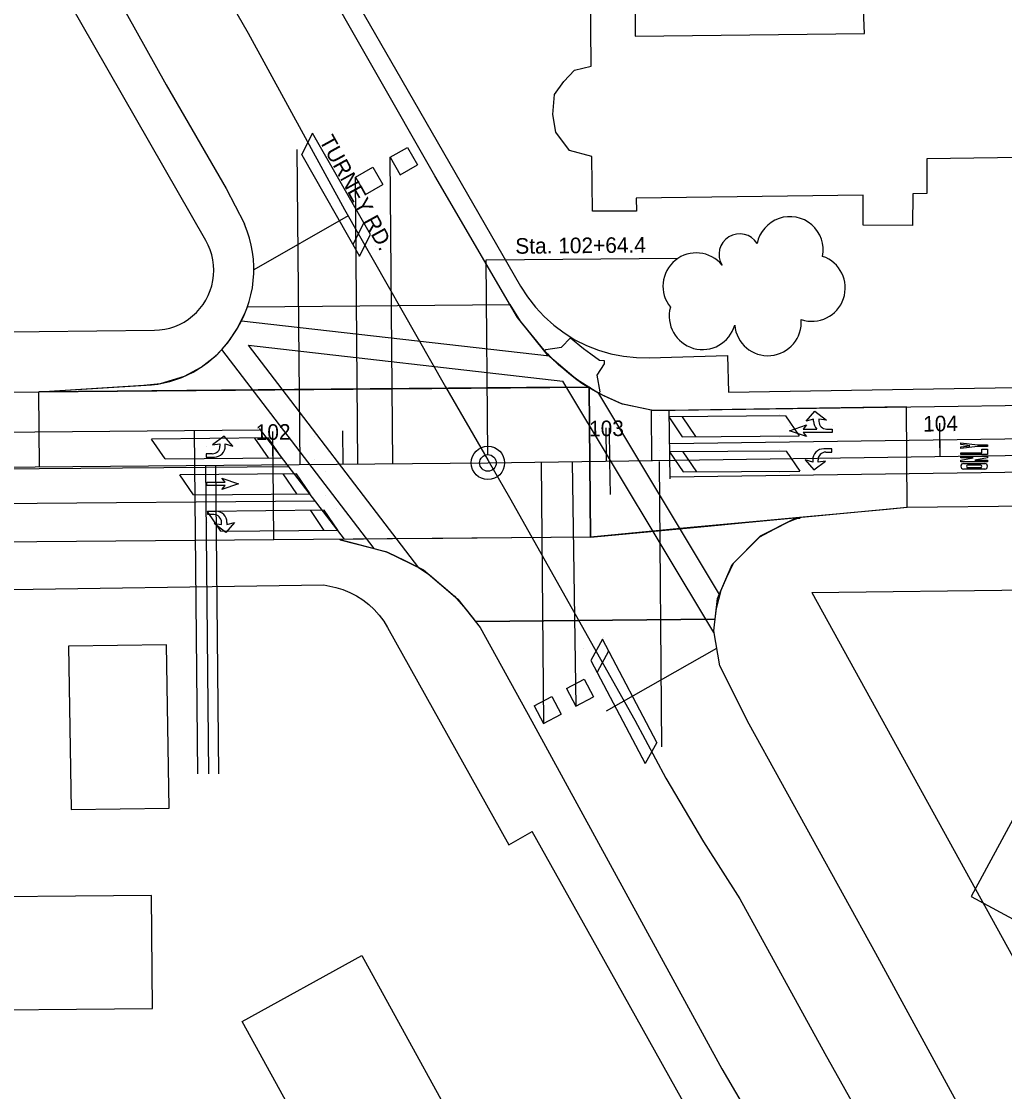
# Model space of a CAD drawing. Extents: x -2233 to 187241, y 4582 to 150524.
# Drawn here: x 110067.4 to 110362.1, y 59307.9 to 59628.8 of the extents above; entities that cross this region are included whole.
import ezdxf

# ---------------------------------------------------------------- set-up
doc = ezdxf.new("R2010")
doc.units = 0
for name, color, linetype in [('AP_X_Misc', 7, 'Continuous'), ('BLDG', 7, 'Continuous'), ('GE_X_CL_100', 7, 'Continuous'), ('GE_X_CL_20', 7, 'Continuous'), ('GE_X_CL_2000', 7, 'Continuous'), ('GE_X_CL_50', 7, 'Continuous'), ('PM_P_Cells', 7, 'Continuous'), ('PM_P_Channelizing_Line', 7, 'Continuous'), ('PM_P_CL_Double_Solid', 7, 'Continuous'), ('PM_P_Crosswalk', 7, 'Continuous'), ('PM_P_Stop_Line', 7, 'Continuous'), ('PM_P_Text', 7, 'Continuous'), ('PV_P_Curb_Ramp', 7, 'Continuous'), ('ROAD', 7, 'Continuous'), ('RW_X_Fee_RW', 7, 'Continuous'), ('SG_P_Detection', 7, 'Continuous'), ('TREES', 7, 'Continuous')]:
    doc.layers.add(name, color=color, linetype=linetype)

msp = doc.modelspace()

# ---------------------------------------------------------------- linework, layer by layer
at = {"layer": 'AP_X_Misc'}
for p, q in [((110072.78, 59495.23), (110072.58, 59517.73)), ((110237.77, 59496.68), (110237.58, 59519.18)), ((110256.34, 59497.13), (110256.2, 59512.13)), ((110332.76, 59498.24), (110332.63, 59513.24)), ((110142.98, 59473.35), (110142.78, 59495.84)), ((110237.97, 59474.18), (110237.77, 59496.68)), ((110332.89, 59483.14), (110332.76, 59498.24))]:
    msp.add_line(p, q, dxfattribs=at)
for points in [[(110072.58, 59517.73), (110104.09, 59519.71), (110109.1, 59520.24), (110116.2, 59522.4), (110121.22, 59525.11), (110125.74, 59528.68), (110129.1, 59532.38), (110131.81, 59536.32), (110134.36, 59541.23), (110135.14, 59543.28), (110213.72, 59543.97), (110216.86, 59538.98), (110223.94, 59530.24), (110226.83, 59527.35), (110231.76, 59523.16), (110236.09, 59519.99), (110237.42, 59519.18), (110218.77, 59519.02), (110160.18, 59518.5), (110127.35, 59518.21), (110096.1, 59517.93)], [(110332.63, 59513.24), (110260.8, 59512.19), (110256.61, 59512.13), (110254.2, 59512.65), (110247.28, 59514.16), (110241.89, 59516.57), (110238.33, 59518.57), (110237.58, 59519.18), (110237.97, 59474.18), (110273.14, 59477.5), (110301.72, 59480.2), (110326.85, 59482.57), (110332.89, 59483.14)], [(110162.76, 59473.41), (110167.4, 59472.25), (110172.26, 59470.99), (110177.12, 59469.61), (110182.07, 59467.21), (110186.33, 59465.14), (110189.68, 59462.85), (110193.74, 59459.38), (110197.2, 59456.43), (110200.55, 59452.59), (110202.49, 59450.12), (110203.47, 59448.88), (110275.36, 59449.51), (110275.73, 59452.83), (110277.13, 59458.26), (110278.79, 59462.18), (110280.8, 59466.33), (110284.26, 59469.81), (110288.66, 59474.24), (110292.95, 59476.56), (110297.49, 59478.88), (110300.56, 59480.09), (110287.73, 59478.88), (110267.91, 59477.01), (110249.29, 59475.25), (110237.92, 59474.18), (110214.34, 59473.97), (110193.67, 59473.79), (110177.03, 59473.65)]]:
    msp.add_lwpolyline(points, close=True, dxfattribs=at)
at = {"layer": 'BLDG'}
for points in [[(110251.27, 59638.74), (110251.33, 59624.37), (110320.12, 59625.2), (110319.25, 59644.45)], [(110388.19, 59588.37), (110338.79, 59587.63), (110338.76, 59577.18), (110334.53, 59577.15), (110334.44, 59567.59), (110319.63, 59567.78), (110319.63, 59576.7), (110251.62, 59575.87), (110251.72, 59571.89), (110238.5, 59571.88), (110238.39, 59588.37), (110231.6, 59590.16), (110227.54, 59595.58), (110226.62, 59600.97), (110227.12, 59606.88), (110229.98, 59610.82), (110233.15, 59614.2), (110238.17, 59615.43), (110237.98, 59638.47)]]:
    msp.add_lwpolyline(points, dxfattribs=at)
for points in [[(110378.28, 59352.16), (110396.6, 59386), (110414.97, 59376.05), (110424.32, 59393.34), (110405.97, 59403.27), (110424.27, 59437.1), (110397.99, 59451.32), (110352.02, 59366.37)], [(110111.68, 59392.91), (110110.89, 59441.88), (110081.5, 59441.41), (110082.29, 59392.45)], [(110038.31, 59332.14), (110106.61, 59332.74), (110106.31, 59366.71), (110038.02, 59366.12)], [(110169.36, 59348.65), (110206.85, 59280.54), (110170.98, 59260.79), (110133.5, 59328.92)]]:
    msp.add_lwpolyline(points, close=True, dxfattribs=at)
at = {"layer": 'GE_X_CL_100'}
for p, q in [((110342.76, 59498.38), (110342.61, 59508.38)), ((110142.78, 59495.84), (110142.69, 59505.84)), ((110242.77, 59496.93), (110242.62, 59506.93))]:
    msp.add_line(p, q, dxfattribs=at)
msp.add_circle((110207.2, 59496.41), 5, dxfattribs=at)
msp.add_circle((110207.2, 59496.41), 5, dxfattribs=at)
at = {"layer": 'GE_X_CL_20'}
for p, q in [((110207.2, 59496.41), (110955.68, 59507.28)), ((109868.59, 59493.43), (110207.2, 59496.41))]:
    msp.add_line(p, q, dxfattribs=at)
at = {"layer": 'GE_X_CL_2000'}
for p, q in [((110207.2, 59496.41), (110955.68, 59507.28)), ((109868.59, 59493.43), (110207.2, 59496.41))]:
    msp.add_line(p, q, dxfattribs=at)
for points in [[(109980.49, 59891.06), (109998.03, 59860.35), (110019.59, 59824.07), (110044.24, 59782.92), (110087.15, 59709.85), (110109.38, 59670.9), (110118.75, 59654.26), (110135.33, 59625.36), (110164.25, 59572.39), (110194.51, 59519.21), (110207.31, 59497.1)], [(110207.31, 59497.1), (110213.69, 59486.07), (110251.26, 59419.29), (110260.51, 59401.88), (110271.8, 59382.77), (110282.72, 59365.7), (110308.21, 59319.29), (110329.38, 59281.54), (110342.24, 59258.86), (110351.38, 59242.1)]]:
    msp.add_lwpolyline(points, dxfattribs=at)
at = {"layer": 'GE_X_CL_50'}
for p, q in [((110206.67, 59557.29), (110264.02, 59557.8)), ((110207.18, 59498.91), (110206.67, 59557.29)), ((110242.77, 59496.93), (110242.7, 59501.93)), ((110342.76, 59498.38), (110342.69, 59503.38)), ((110142.78, 59495.84), (110142.73, 59500.84))]:
    msp.add_line(p, q, dxfattribs=at)
msp.add_circle((110207.2, 59496.41), 2.5, dxfattribs=at)
msp.add_circle((110207.2, 59496.41), 2.5, dxfattribs=at)
at = {"layer": 'PM_P_Cells'}
for p, q in [((110302.58, 59508.9), (110305.14, 59511.9)), ((110305.14, 59511.9), (110308.66, 59509.24)), ((110304.82, 59509.57), (110302.58, 59508.9)), ((110304.82, 59508.9), (110304.82, 59509.57)), ((110308.66, 59509.24), (110306.42, 59509.57)), ((110306.42, 59509.57), (110306.42, 59508.87)), ((110297.64, 59506.07), (110302.64, 59507.81)), ((110297.64, 59507.74), (110297.64, 59507.74)), ((110302.64, 59504.34), (110297.64, 59506.07)), ((110302.64, 59507.81), (110301.64, 59506.57)), ((110310.39, 59505.57), (110301.64, 59505.57)), ((110301.64, 59505.57), (110302.64, 59504.34)), ((110308.72, 59506.57), (110310.39, 59506.57)), ((110310.39, 59507.74), (110310.39, 59507.74)), ((110310.39, 59506.57), (110310.39, 59505.57)), ((110128.16, 59504.49), (110124.64, 59501.82)), ((110124.64, 59501.82), (110126.88, 59502.15)), ((110126.88, 59502.15), (110126.88, 59501.45)), ((110130.72, 59501.49), (110128.16, 59504.49)), ((110128.48, 59501.49), (110128.48, 59502.15)), ((110128.48, 59502.15), (110130.72, 59501.49)), ((110348.94, 59501.91), (110348.94, 59502.41)), ((110348.94, 59502.41), (110353.94, 59501.83)), ((110351.61, 59501.58), (110348.94, 59501.91)), ((110353.94, 59501.83), (110356.94, 59501.83)), ((110356.94, 59501.83), (110356.94, 59501.33)), ((110122.72, 59501.49), (110122.72, 59501.49)), ((110124.58, 59499.15), (110122.72, 59499.15)), ((110122.72, 59499.15), (110122.72, 59498.15)), ((110130.72, 59501.49), (110130.72, 59501.49)), ((110310.32, 59500.65), (110307.84, 59500.65)), ((110308.45, 59499.65), (110310.32, 59499.65)), ((110310.32, 59499.65), (110310.32, 59500.65)), ((110348.94, 59501.25), (110351.61, 59501.58)), ((110353.94, 59501.33), (110348.94, 59500.75)), ((110348.94, 59500.75), (110348.94, 59501.25)), ((110348.94, 59498.91), (110348.94, 59499.41)), ((110348.94, 59499.41), (110355.28, 59499.41)), ((110356.94, 59498.91), (110348.94, 59498.91)), ((110348.94, 59498.5), (110348.94, 59498.5)), ((110356.94, 59501.33), (110353.94, 59501.33)), ((110355.28, 59499.41), (110355.28, 59500.58)), ((110355.28, 59500.58), (110356.94, 59500.58)), ((110356.94, 59500.58), (110356.94, 59498.91)), ((110356.94, 59498.5), (110356.94, 59498.5)), ((110122.72, 59498.15), (110125.2, 59498.15)), ((110302.32, 59497.32), (110302.32, 59497.32)), ((110304.56, 59496.65), (110302.32, 59497.32)), ((110302.32, 59497.32), (110304.88, 59494.32)), ((110304.56, 59497.32), (110304.56, 59496.65)), ((110304.88, 59494.32), (110308.4, 59496.99)), ((110306.16, 59496.65), (110306.16, 59497.36)), ((110308.4, 59496.99), (110306.16, 59496.65)), ((110310.32, 59497.32), (110310.32, 59497.32)), ((110348.94, 59497.91), (110348.94, 59498.41)), ((110348.94, 59498.41), (110356.94, 59498.41)), ((110348.94, 59497.25), (110352.69, 59497.91)), ((110352.69, 59497.91), (110348.94, 59497.91)), ((110348.94, 59496.75), (110348.94, 59497.25)), ((110356.94, 59496.75), (110348.94, 59496.75)), ((110349.78, 59496.25), (110356.11, 59496.25)), ((110354.95, 59495.75), (110350.94, 59495.75)), ((110356.94, 59497.91), (110353.19, 59497.25)), ((110353.19, 59497.25), (110356.94, 59497.25)), ((110356.94, 59498.41), (110356.94, 59497.91)), ((110356.94, 59497.25), (110356.94, 59496.75)), ((110350.94, 59494.58), (110349.78, 59494.58)), ((110350.94, 59495.08), (110350.94, 59494.58)), ((110350.94, 59494.58), (110350.94, 59495.08)), ((110350.94, 59495.08), (110354.95, 59495.08)), ((110354.95, 59494.58), (110350.94, 59494.58)), ((110354.95, 59494.58), (110354.95, 59495.08)), ((110354.95, 59495.08), (110354.95, 59494.58)), ((110356.11, 59494.58), (110354.95, 59494.58)), ((110122.97, 59489.65), (110122.97, 59490.65)), ((110122.97, 59490.65), (110128.47, 59490.65)), ((110122.97, 59490.15), (110122.97, 59490.15)), ((110128.47, 59489.65), (110122.97, 59489.65)), ((110128.47, 59490.65), (110127.47, 59491.89)), ((110127.47, 59491.89), (110132.47, 59490.15)), ((110132.47, 59490.15), (110127.47, 59488.41)), ((110127.47, 59488.41), (110128.47, 59489.65)), ((110132.47, 59490.15), (110132.47, 59490.15)), ((110123.2, 59480.91), (110123.2, 59481.91)), ((110123.2, 59481.91), (110125.67, 59481.91)), ((110125.06, 59480.91), (110123.2, 59480.91)), ((110123.2, 59478.58), (110123.2, 59478.58)), ((110128.64, 59475.58), (110125.12, 59478.24)), ((110125.12, 59478.24), (110127.36, 59477.91)), ((110127.36, 59477.91), (110127.36, 59478.61)), ((110131.2, 59478.58), (110128.64, 59475.58)), ((110128.96, 59478.58), (110128.96, 59477.91)), ((110128.96, 59477.91), (110131.2, 59478.58)), ((110131.2, 59478.58), (110131.2, 59478.58))]:
    msp.add_line(p, q, dxfattribs=at)
msp.add_lwpolyline([(110301.64, 59506.57), (110305.75, 59506.57)], dxfattribs=at)
for centre, radius, start, end in [((110308.11, 59508.85), 3.28, 179.0915, 224.0466), ((110308.72, 59508.87), 2.3, 180, 270), ((110124.58, 59501.45), 2.3, 270, 0), ((110125.2, 59501.44), 3.28, 270, 0.9085), ((110307.84, 59497.37), 3.28, 90, 180.9085), ((110308.45, 59497.36), 2.3, 90, 180), ((110349.78, 59495.41), 0.833, 90, 270), ((110350.94, 59495.41), 0.333, 90, 270), ((110354.95, 59495.41), 0.333, 270, 90), ((110356.11, 59495.41), 0.833, 270, 90), ((110125.06, 59478.61), 2.3, 0, 90), ((110125.67, 59478.63), 3.28, 359.0915, 90)]:
    msp.add_arc(centre, radius, start, end, dxfattribs=at)
at = {"layer": 'PM_P_Channelizing_Line'}
for p, q in [((110261.69, 59502.2), (110606.03, 59507.2)), ((110022.11, 59494.28), (110147.48, 59495.39)), ((110155.46, 59484.96), (110050.88, 59484.03))]:
    msp.add_line(p, q, dxfattribs=at)
at = {"layer": 'PM_P_CL_Double_Solid'}
for p, q in [((110022.01, 59505.28), (110138.76, 59506.31)), ((110261.84, 59492.21), (110616.44, 59497.35))]:
    msp.add_line(p, q, dxfattribs=at)
at = {"layer": 'PM_P_Crosswalk'}
for p, q in [((110133.32, 59539), (110225.68, 59528.49)), ((110186.44, 59465), (110135.39, 59531.71)), ((110135.39, 59531.71), (110229.63, 59520.99)), ((110173.09, 59470.78), (110127.44, 59530.42)), ((110274.91, 59445.56), (110229.63, 59520.99)), ((110276.59, 59457), (110240.45, 59517.21))]:
    msp.add_line(p, q, dxfattribs=at)
at = {"layer": 'PM_P_Stop_Line'}
for p, q in [((110165.33, 59570.49), (110137.01, 59554.38)), ((110261.85, 59491.69), (110261.55, 59512.2)), ((110164.21, 59473.53), (110138.75, 59506.79)), ((110242.73, 59422.05), (110275.81, 59440.81))]:
    msp.add_line(p, q, dxfattribs=at)
at = {"layer": 'PM_P_Text'}
for p, q in [((110150.87, 59495.92), (110150.04, 59590.4)), ((110178.69, 59496.16), (110177.88, 59588.08)), ((110168.22, 59496.07), (110167.46, 59582.11)), ((110119.19, 59506.14), (110120.1, 59403.15)), ((110163.78, 59496.03), (110163.69, 59506.03)), ((110243.77, 59496.94), (110243.62, 59506.94)), ((110122.58, 59495.67), (110123.4, 59403.18)), ((110125.58, 59495.69), (110126.4, 59403.2)), ((110223.15, 59496.55), (110223.84, 59418.26)), ((110232.49, 59496.78), (110233.56, 59423.42)), ((110243.91, 59486.94), (110243.77, 59496.94)), ((110258.52, 59496.86), (110259.27, 59411.25))]:
    msp.add_line(p, q, dxfattribs=at)
at = {"layer": 'PV_P_Curb_Ramp'}
msp.add_lwpolyline([(110224.15, 59530.13), (110224.53, 59530.45), (110229.26, 59531.14), (110231.94, 59533.95), (110235.81, 59530.76), (110238, 59529.1), (110240.62, 59527.21), (110242.08, 59527.14), (110242.03, 59526.12), (110239.85, 59522.76), (110240.71, 59517.79), (110240.5, 59517.34), (110239.45, 59517.85), (110237.58, 59518.94), (110235.38, 59520.29), (110233.4, 59521.66), (110231.45, 59523.25), (110229.92, 59524.52), (110228.39, 59525.86), (110226.88, 59527.32), (110225.43, 59528.74), (110224.66, 59529.46)], close=True, dxfattribs=at)
at = {"layer": 'ROAD'}
for p, q in [((110135.14, 59543.28), (110213.72, 59543.97)), ((110256.2, 59512.13), (110919.2, 59521.75)), ((110021.58, 59517.28), (110072.58, 59517.73)), ((110072.58, 59517.73), (110106.33, 59519.85)), ((110072.58, 59517.73), (110237.58, 59519.18)), ((110237.97, 59474.18), (110332.89, 59483.14)), ((110332.89, 59483.14), (110442.97, 59484.5)), ((110142.98, 59473.35), (110059.98, 59472.61)), ((110237.97, 59474.18), (110142.98, 59473.35)), ((110275.36, 59449.51), (110203.47, 59448.88))]:
    msp.add_line(p, q, dxfattribs=at)
for points in [[(110256.2, 59512.23), (110247.5, 59514.06), (110240.48, 59517.2), (110233.65, 59521.55), (110225.04, 59528.88), (110216.04, 59539.99), (110191.31, 59582.54), (110118.93, 59709.36), (110052.23, 59823.22), (109992.15, 59921.86)], [(109993.05, 59818.6), (109998.28, 59809.12), (110027.42, 59758.31), (110077.35, 59669.8), (110110.71, 59609.85), (110128.73, 59578.72), (110134.1, 59568.34), (110134.21, 59568)], [(110500.24, 59028.14), (110497, 59033.97), (110407.47, 59195), (110323.47, 59349.24), (110285.49, 59418.02), (110276.67, 59435.6), (110274.96, 59446.01), (110276.06, 59455.76), (110280.39, 59465.92), (110288.93, 59474.51), (110299.18, 59479.74), (110300.82, 59479.88)], [(110162.76, 59473.41), (110162.93, 59473.4), (110176.56, 59469.88), (110187.86, 59464.4), (110198.18, 59455.59), (110204.91, 59447.06), (110220.32, 59418.96), (110277.3, 59314.73), (110306.26, 59265.16)]]:
    msp.add_lwpolyline(points, dxfattribs=at)
for centre, radius, start, end in [((110102.9, 59554.44), 34.12, 325.3465, 23.4134), ((110103.12, 59552.61), 32.92, 275.5964, 327.7335)]:
    msp.add_arc(centre, radius, start, end, dxfattribs=at)
at = {"layer": 'RW_X_Fee_RW'}
for p, q in [((110122.63, 59563.15), (110067.59, 59659.24)), ((110255.56, 59527.96), (110278.96, 59528.68)), ((110278.96, 59528.68), (110279.3, 59517.69)), ((110304.28, 59457.52), (110480.21, 59459.77)), ((110304.28, 59457.52), (110391.88, 59298.63)), ((110177.13, 59447.07), (110213.51, 59381.92)), ((110213.51, 59381.92), (110220.5, 59385.82))]:
    msp.add_line(p, q, dxfattribs=at)
for points in [[(110124.05, 59710.81), (110152.77, 59660.94), (110181.43, 59611.19), (110216.96, 59549.48)], [(110107.22, 59536.2), (110108.77, 59536.29), (110110.32, 59536.51), (110111.84, 59536.86), (110113.32, 59537.34), (110114.75, 59537.95), (110116.13, 59538.68), (110117.44, 59539.53), (110118.67, 59540.49), (110119.81, 59541.55), (110120.86, 59542.7), (110121.8, 59543.94), (110122.64, 59545.26), (110123.35, 59546.65), (110123.94, 59548.09), (110124.41, 59549.58), (110124.74, 59551.1), (110124.94, 59552.65), (110125.01, 59554.21), (110124.94, 59555.76), (110124.74, 59557.31), (110124.4, 59558.83), (110123.94, 59560.32), (110123.35, 59561.76), (110122.63, 59563.15)], [(110216.96, 59549.48), (110219.04, 59546.22), (110221.41, 59543.16), (110224.03, 59540.32), (110226.91, 59537.73), (110230, 59535.41), (110233.29, 59533.38), (110236.75, 59531.65), (110240.34, 59530.24), (110244.06, 59529.16), (110247.85, 59528.41), (110251.7, 59528.01), (110255.56, 59527.96)], [(110002.93, 59535), (110003.42, 59535.01), (110107.22, 59536.2)], [(110279.3, 59517.69), (110599.02, 59522.84), (110743.01, 59525.17)], [(110010.75, 59457.66), (110050.75, 59458.26), (110157.97, 59459.85)], [(110157.97, 59459.85), (110161.59, 59459.08), (110163.74, 59458.42), (110165.81, 59457.57), (110167.8, 59456.54), (110169.69, 59455.33), (110171.46, 59453.96), (110173.11, 59452.44), (110174.61, 59450.77), (110175.95, 59448.98), (110177.13, 59447.07)], [(110298.51, 59246.13), (110279.01, 59281.05), (110259.51, 59315.98), (110240, 59350.9), (110220.5, 59385.82)]]:
    msp.add_lwpolyline(points, dxfattribs=at)
at = {"layer": 'SG_P_Detection'}
for p, q in [((110151.38, 59588.87), (110154.61, 59595.32)), ((110171.97, 59564.92), (110154.61, 59595.32)), ((110155.25, 59593.38), (110155.25, 59593.38)), ((110150.04, 59590.4), (110150.04, 59590.4)), ((110151.38, 59588.87), (110168.74, 59558.47)), ((110177.88, 59588.08), (110183.08, 59591.06)), ((110183.08, 59591.06), (110186.07, 59585.85)), ((110177.88, 59588.08), (110180.86, 59582.87)), ((110180.86, 59582.87), (110186.07, 59585.85)), ((110167.46, 59582.11), (110172.67, 59585.09)), ((110167.46, 59582.11), (110170.45, 59576.9)), ((110172.67, 59585.09), (110175.65, 59579.89)), ((110170.45, 59576.9), (110175.65, 59579.89)), ((110166.76, 59561.95), (110169.98, 59568.39)), ((110168.74, 59558.47), (110171.97, 59564.92)), ((110173.64, 59561.27), (110173.64, 59561.27)), ((110168.43, 59558.29), (110168.43, 59558.29)), ((110258.49, 59510.75), (110258.49, 59510.75)), ((110296.41, 59510.51), (110261.41, 59510.26)), ((110261.41, 59510.26), (110265.45, 59504.29)), ((110265.41, 59510.29), (110269.45, 59504.32)), ((110294.48, 59511.06), (110294.48, 59511.06)), ((110296.41, 59510.51), (110300.45, 59504.53)), ((110141.37, 59503.9), (110106.37, 59503.57)), ((110110.42, 59497.61), (110106.37, 59503.57)), ((110119.24, 59504.15), (110119.24, 59504.15)), ((110141.42, 59497.9), (110137.37, 59503.86)), ((110145.42, 59497.93), (110141.37, 59503.9)), ((110155.24, 59504.46), (110155.24, 59504.46)), ((110258.55, 59503.75), (110258.55, 59503.75)), ((110265.45, 59504.29), (110300.45, 59504.53)), ((110294.55, 59504.06), (110294.55, 59504.06)), ((110258.49, 59500.27), (110258.49, 59500.27)), ((110296.64, 59499.96), (110261.64, 59499.72)), ((110261.64, 59499.72), (110265.68, 59493.75)), ((110265.64, 59499.75), (110269.68, 59493.77)), ((110294.48, 59500.59), (110294.48, 59500.59)), ((110296.64, 59499.96), (110300.68, 59493.99)), ((110110.42, 59497.61), (110145.42, 59497.93)), ((110119.3, 59497.15), (110119.3, 59497.15)), ((110155.3, 59497.46), (110155.3, 59497.46)), ((110149.86, 59493.14), (110114.85, 59492.81)), ((110118.91, 59486.85), (110114.85, 59492.81)), ((110122.55, 59493.38), (110122.55, 59493.38)), ((110149.91, 59487.14), (110145.86, 59493.1)), ((110153.91, 59487.17), (110149.86, 59493.14)), ((110158.55, 59493.7), (110158.55, 59493.7)), ((110258.55, 59493.27), (110258.55, 59493.27)), ((110265.68, 59493.75), (110300.68, 59493.99)), ((110294.55, 59493.59), (110294.55, 59493.59)), ((110118.91, 59486.85), (110153.91, 59487.17)), ((110122.61, 59486.38), (110122.61, 59486.38)), ((110158.61, 59486.7), (110158.61, 59486.7)), ((110161.73, 59482.68), (110161.73, 59482.68)), ((110158.1, 59482.2), (110123.1, 59481.88)), ((110127.16, 59475.92), (110123.1, 59481.88)), ((110125.73, 59482.37), (110125.73, 59482.37)), ((110158.16, 59476.2), (110154.1, 59482.17)), ((110162.16, 59476.24), (110158.1, 59482.2)), ((110127.16, 59475.92), (110162.16, 59476.24)), ((110125.79, 59475.37), (110125.79, 59475.37)), ((110161.79, 59475.68), (110161.79, 59475.68)), ((110241.91, 59443.93), (110241.91, 59443.93)), ((110241.49, 59443.53), (110238.05, 59437.19)), ((110257.81, 59412.56), (110241.49, 59443.53)), ((110235.73, 59440.64), (110235.73, 59440.64)), ((110243.35, 59439.99), (110239.91, 59433.65)), ((110238.05, 59437.19), (110254.37, 59406.23)), ((110230.74, 59428.72), (110236.04, 59431.53)), ((110236.04, 59431.53), (110238.86, 59426.23)), ((110230.74, 59428.72), (110233.56, 59423.42)), ((110221.03, 59423.56), (110226.33, 59426.37)), ((110226.33, 59426.37), (110229.14, 59421.07)), ((110233.56, 59423.42), (110238.86, 59426.23)), ((110221.03, 59423.56), (110223.84, 59418.26)), ((110223.84, 59418.26), (110229.14, 59421.07)), ((110257.81, 59412.56), (110254.37, 59406.23)), ((110259.27, 59411.25), (110259.27, 59411.25)), ((110253.09, 59407.97), (110253.09, 59407.97))]:
    msp.add_line(p, q, dxfattribs=at)
at = {"layer": 'TREES'}
for centre, radius, start, end in [((110297.7, 59560.29), 10, 348.9264, 168.9264), ((110282.64, 59558.98), 6.16, 31.7028, 211.7028), ((110269.65, 59549.42), 10, 39.1772, 219.1772), ((110304.3, 59548.9), 10, 251.2672, 71.2672), ((110271.53, 59540.42), 10, 164.4225, 344.4225), ((110291.12, 59538.58), 10, 184.8744, 4.8744)]:
    msp.add_arc(centre, radius, start, end, dxfattribs=at)

# ---------------------------------------------------------------- texts
at = {"layer": 'GE_X_CL_50'}
for s, rotation, p in [('TURNEY RD.', 298.8473, (110156.51, 59593.13)), ('Sta. 102+64.4', 0.5049, (110215.42, 59559.15)), ('102', 0.5049, (110137.61, 59503.3)), ('103', 0.8319, (110237.54, 59504.35)), ('104', 0.8319, (110337.68, 59505.81))]:
    msp.add_text(s, height=4.68, rotation=rotation, dxfattribs=at).set_placement(p)

doc.saveas('drawing.dxf')
